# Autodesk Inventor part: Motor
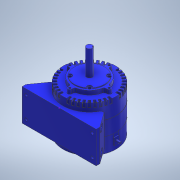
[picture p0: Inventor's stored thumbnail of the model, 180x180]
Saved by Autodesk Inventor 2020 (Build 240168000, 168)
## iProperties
Created: 2019-03
Part Number: Motor
Material: Generic
Document SubType Name: Modeling
Designer: user
Density: 1 g/cm^3
Appearance: Default
Author: user
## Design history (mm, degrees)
derived "Ensamble motor 2.iam"
body "Solid1"
node "Base motor.ipt:1"
sketch "Sketch2"
  geometry: 1 further point
  dimensions: "d0" = 10 dimension on point (149.984, 0)
node "Motenergy ME1003.ipt:1"
